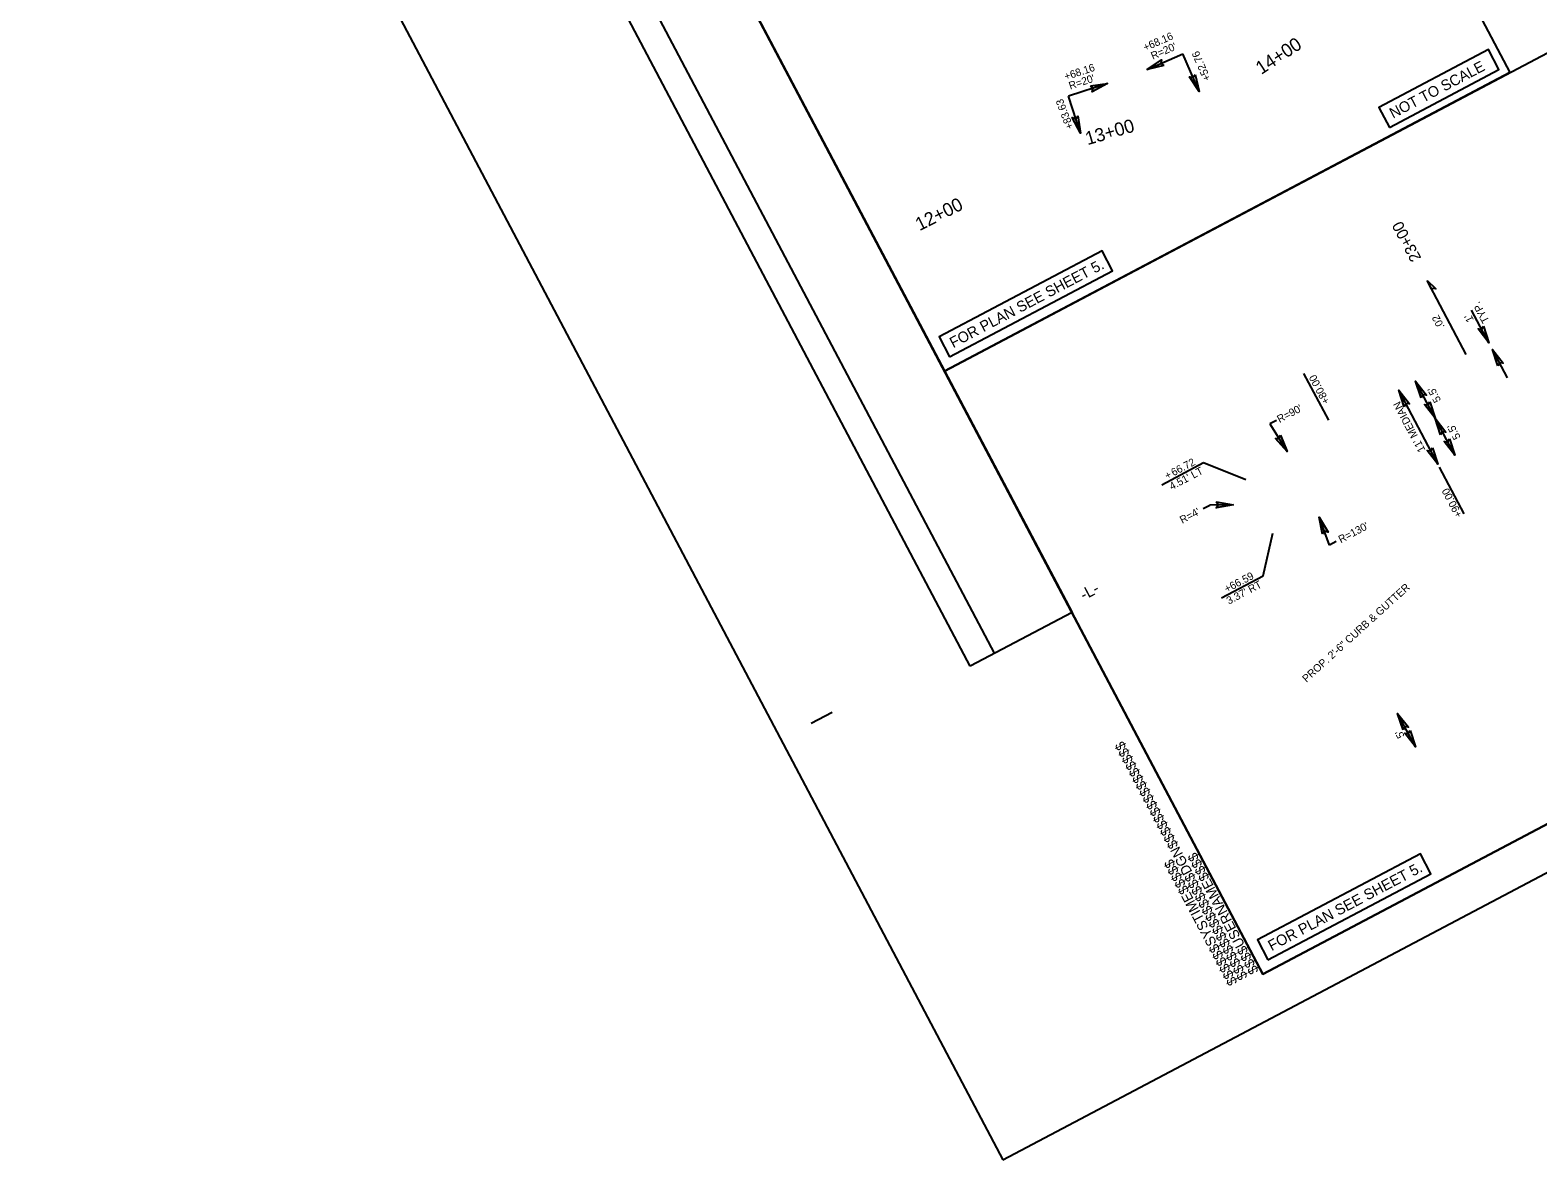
# Model space of a CAD drawing. Extents: x 1487555 to 1489555, y 497613 to 499367.
# Drawn here: x 1487555 to 1488347, y 497613 to 498206 of the extents above; entities that cross this region are included whole.
import ezdxf

# ---------------------------------------------------------------- set-up
doc = ezdxf.new("R2010")
doc.units = 0
for name, color, linetype in [('Prop Dimension', 7, 'Continuous'), ('Prop Dimension Text', 7, 'Continuous'), ('Prop Grid Mask', 7, 'Continuous'), ('Prop Horizontal Alignment Curve and Spiral Data', 7, 'Continuous'), ('Prop Horizontal Alignment Direction Label', 7, 'Continuous'), ('Prop Horizontal Alignment Tick Label', 7, 'Continuous'), ('Prop Superelevation  Arrow CELL', 7, 'Continuous'), ('Prop Superelevation Label', 7, 'Continuous'), ('Prop Terminator CELL', 7, 'Continuous'), ('Sheet Block Revision CELL', 7, 'Continuous'), ('Sheet Plan CELL', 7, 'Continuous'), ('Sheet Plot Border Outside CELL', 7, 'Continuous')]:
    doc.layers.add(name, color=color, linetype=linetype)

msp = doc.modelspace()

# ---------------------------------------------------------------- linework, layer by layer
at = {"layer": 'Prop Dimension'}
for p, q in [((1488141.92, 498185.74), (1488160.74, 498193.94)), ((1488169.32, 498174.27), (1488160.74, 498193.94)), ((1488121.16, 498178.46), (1488100.57, 498171.68)), ((1488106.92, 498152.38), (1488100.57, 498171.68)), ((1488321.55, 498042.19), (1488312.51, 498059.3)), ((1488331.33, 498023.66), (1488323.42, 498038.65)), ((1488237.39, 498001.41), (1488224.42, 498025.96)), ((1488293.39, 498002.44), (1488283.11, 498021.89)), ((1488294.82, 497978.32), (1488274.27, 498017.22)), ((1488210, 498001.35), (1488206.47, 497999.49)), ((1488206.47, 497999.49), (1488215.53, 497985.06)), ((1488303.66, 497982.99), (1488293.39, 498002.44)), ((1488149.72, 497967.55), (1488171.62, 497979.12)), ((1488171.62, 497979.12), (1488193.78, 497970.27)), ((1488308.63, 497952.15), (1488295.66, 497976.71)), ((1488171.38, 497954.99), (1488174.92, 497956.86)), ((1488187.26, 497957.02), (1488174.92, 497956.86)), ((1488237.85, 497935.82), (1488232.44, 497950.45)), ((1488203.02, 497919.66), (1488208.05, 497942.11)), ((1488241.38, 497937.69), (1488237.85, 497935.82)), ((1488181.11, 497908.09), (1488203.02, 497919.66)), ((1488283.09, 497829.74), (1488273.58, 497847.33))]:
    msp.add_line(p, q, dxfattribs=at)
at = {"layer": 'Prop Grid Mask'}
for points in [[(1488269.32, 498155.36), (1488326.85, 498185.74), (1488321.33, 498196.2), (1488263.8, 498165.82)], [(1488038.11, 498034.75), (1488123.81, 498080), (1488118.29, 498090.46), (1488032.59, 498045.21)], [(1488205.47, 497717.8), (1488291.17, 497763.05), (1488285.65, 497773.51), (1488199.95, 497728.26)]]:
    msp.add_lwpolyline(points, close=True, dxfattribs=at)
at = {"layer": 'Prop Superelevation  Arrow CELL'}
msp.add_line((1488309.64, 498035.9), (1488289.1, 498074.81), dxfattribs=at)
msp.add_lwpolyline([(1488289.1, 498074.81), (1488293.67, 498070.44), (1488291.26, 498070.72)], close=True, dxfattribs=at)
at = {"layer": 'Prop Terminator CELL'}
for points in [[(1488150.79, 498187.92), (1488141.92, 498185.74), (1488149.57, 498190.83), (1488149.16, 498188.9)], [(1488167.14, 498183.14), (1488169.32, 498174.27), (1488164.24, 498181.92), (1488166.16, 498181.51)], [(1488112.12, 498177.12), (1488121.16, 498178.46), (1488113.06, 498174.11), (1488113.65, 498175.99)], [(1488105.58, 498161.42), (1488106.92, 498152.38), (1488102.58, 498160.48), (1488104.45, 498159.89)], [(1488318.72, 498050.87), (1488321.55, 498042.19), (1488315.91, 498049.44), (1488317.86, 498049.17)], [(1488326.25, 498029.97), (1488323.42, 498038.65), (1488329.06, 498031.4), (1488327.1, 498031.67)], [(1488285.95, 498013.21), (1488283.11, 498021.89), (1488288.75, 498014.64), (1488286.8, 498014.91)], [(1488277.1, 498008.54), (1488274.27, 498017.22), (1488279.91, 498009.97), (1488277.96, 498010.24)], [(1488290.55, 498011.12), (1488293.39, 498002.44), (1488287.75, 498009.7), (1488289.7, 498009.43)], [(1488296.22, 497993.76), (1488293.39, 498002.44), (1488299.03, 497995.18), (1488297.07, 497995.45)], [(1488212.05, 497993.51), (1488215.53, 497985.06), (1488209.36, 497991.88), (1488211.32, 497991.75)], [(1488300.83, 497991.67), (1488303.66, 497982.99), (1488298.02, 497990.24), (1488299.97, 497989.97)], [(1488291.98, 497987), (1488294.82, 497978.32), (1488289.17, 497985.57), (1488291.13, 497985.3)], [(1488178.24, 497958.45), (1488187.26, 497957.02), (1488178.23, 497955.3), (1488179.36, 497956.92)], [(1488234.11, 497941.48), (1488232.44, 497950.45), (1488237.08, 497942.52), (1488235.18, 497943.05)], [(1488276.49, 497838.67), (1488273.58, 497847.33), (1488279.29, 497840.13), (1488277.33, 497840.38)], [(1488280.17, 497838.39), (1488283.09, 497829.74), (1488277.38, 497836.94), (1488279.33, 497836.68)]]:
    msp.add_lwpolyline(points, close=True, dxfattribs=at)
at = {"layer": 'Sheet Block Revision CELL'}
msp.add_line((1488061.82, 497878.97), (1487692.63, 498578.12), dxfattribs=at)
msp.add_lwpolyline([(1488048.96, 497872.15), (1487679.78, 498571.32), (1487733.31, 498599.61), (1488102.48, 497900.44)], close=True, dxfattribs=at)
at = {"layer": 'Sheet Plan CELL'}
for p, q in [((1487965.35, 497842.15), (1487976.4, 497847.98)), ((1488202.86, 497710.31), (1488202.86, 497710.31))]:
    msp.add_line(p, q, dxfattribs=at)
for points in [[(1489039.06, 499339.23), (1487712.59, 498638.82), (1488202.86, 497710.31), (1489529.32, 498410.71)], [(1488202.86, 497710.31), (1487712.58, 498638.79), (1488862.13, 499245.82), (1488932.21, 499113.13), (1489109.11, 499206.52), (1489529.32, 498410.71)], [(1488035.48, 498027.26), (1489052.32, 498564.17), (1489219.68, 498247.22), (1488202.84, 497710.3)], [(1487910.18, 498264.56), (1488207.27, 498421.43), (1488332.57, 498184.13), (1488035.48, 498027.26)]]:
    msp.add_lwpolyline(points, close=True, dxfattribs=at)
at = {"layer": 'Sheet Plot Border Outside CELL'}
msp.add_lwpolyline([(1488066.15, 497612.67), (1489554.86, 498398.74), (1489043.57, 499367.04), (1487554.86, 498580.97)], close=True, dxfattribs=at)

# ---------------------------------------------------------------- texts
at = {"layer": 'Prop Dimension Text'}
for s, rotation, p in [('+68.16', 23.61882, (1488140.95, 498195.31)), ("R=20'", 23.61882, (1488145, 498190.85)), ('+68.16', 18.21972, (1488099.18, 498180.04)), ('+52.76', 113.54917, (1488175.54, 498180.78)), ("R=20'", 18.21972, (1488101.55, 498175.2)), ('+83.63', 110.79125, (1488103.39, 498155.27)), ('TYP.', 117.83509, (1488321.97, 498053.69)), ("1'", 117.83509, (1488313.81, 498054.16)), ('+80.00', 117.83509, (1488238.07, 498011.2)), ("5.5'", 117.83509, (1488296.59, 498011.94)), ("R=90'", 27.83509, (1488211.55, 497999.91)), ("11' MEDIAN", 117.83509, (1488288.33, 497985.84)), ("5.5'", 117.83509, (1488306.86, 497992.48)), ('+', 27.83509, (1488152.53, 497970.17)), ("4.51' LT", 27.83509, (1488154.9, 497964.63)), ('66.72', 27.83509, (1488155.87, 497971.93)), ('+90.00', 117.83509, (1488307.87, 497951.58)), ("R=4'", 27.83509, (1488160.42, 497946.94)), ("R=130'", 27.83509, (1488243.79, 497936.7)), ('+66.59', 27.83509, (1488183.88, 497910.69)), ("3.37' RT", 27.83509, (1488184.93, 497904.46)), ('PROP. 2\'-6" CURB & GUTTER', 42.24129, (1488225.72, 497863.39)), ("5'", 117.83509, (1488277.4, 497835.48))]:
    msp.add_text(s, height=4, rotation=rotation, dxfattribs=at).set_placement(p)
at = {"layer": 'Prop Horizontal Alignment Curve and Spiral Data'}
for s, p in [('NOT TO SCALE', (1488271.22, 498159.87)), ('FOR PLAN SEE SHEET 5.', (1488040.03, 498039.27)), ('FOR PLAN SEE SHEET 5.', (1488207.39, 497722.32))]:
    msp.add_text(s, height=5.625, rotation=27.83509, dxfattribs=at).set_placement(p)
at = {"layer": 'Prop Horizontal Alignment Direction Label'}
for s, rotation, p in [('23+00', 117.83509, (1488286.22, 498086.68)), ('-L-', 27.89497, (1488108.67, 497906.6))]:
    msp.add_text(s, height=6, rotation=rotation, dxfattribs=at).set_placement(p)
at = {"layer": 'Prop Horizontal Alignment Tick Label'}
for s, rotation, p in [('14+00', 33.31697, (1488201.94, 498182.86)), ('13+00', 16.21375, (1488110.65, 498145.96)), ('12+00', 26.59503, (1488022.35, 498100.78))]:
    msp.add_text(s, height=7, rotation=rotation, dxfattribs=at).set_placement(p)
at = {"layer": 'Prop Superelevation Label'}
msp.add_text('.02', height=4, rotation=117.89497, dxfattribs=at).set_placement((1488298.45, 498050.65))
at = {"layer": 'Sheet Plan CELL'}
for s, p in [('$$$$$$$$$$$$$$$$DGN$$$$$$$$$$$$$$$$', (1488195, 497708.84)), ('$$$$$$SYSTIME$$$$$', (1488189.64, 497705.98)), ('$$$$USERNAME$$$$', (1488200.79, 497711.91))]:
    msp.add_text(s, height=5.25, rotation=117.8351, dxfattribs=at).set_placement(p)

doc.saveas('drawing.dxf')
